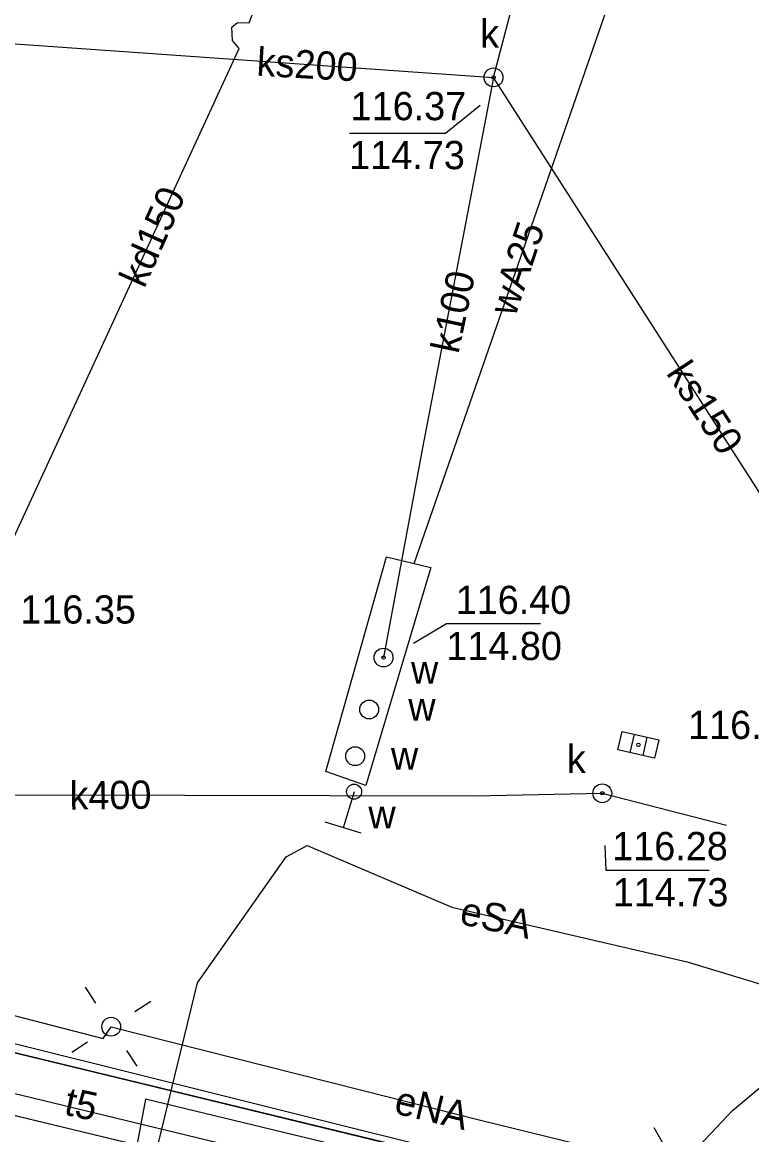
# Model space of a CAD drawing. Extents: x 6424617 to 6425697, y 5665845 to 5667190.
# Drawn here: x 6425547.64 to 6425566.99, y 5666958.69 to 5666988.22 of the extents above; entities that cross this region are included whole.
import ezdxf

# ---------------------------------------------------------------- set-up
doc = ezdxf.new("R2010")
doc.units = 0
for name, color, linetype in [('Warstwa 1', 7, 'Continuous'), ('Warstwa 10', 7, 'Continuous'), ('Warstwa 11', 7, 'Continuous'), ('Warstwa 12', 7, 'Continuous'), ('Warstwa 13', 7, 'Continuous'), ('Warstwa 14', 7, 'Continuous'), ('Warstwa 15', 7, 'Continuous'), ('Warstwa 16', 7, 'Continuous'), ('Warstwa 19', 7, 'Continuous'), ('Warstwa 2', 7, 'Continuous'), ('Warstwa 4', 7, 'Continuous'), ('Warstwa 5', 7, 'Continuous'), ('Warstwa 6', 7, 'Continuous'), ('Warstwa 8', 7, 'Continuous')]:
    doc.layers.add(name, color=color, linetype=linetype)

msp = doc.modelspace()

# ---------------------------------------------------------------- linework, layer by layer
at = {"layer": 'Warstwa 1'}
msp.add_line((6425527.303, 5666965.745), (6425576.814, 5666953.737), dxfattribs=at)
msp.add_line((6425527.303, 5666965.745), (6425576.814, 5666953.737), dxfattribs=at)
at = {"layer": 'Warstwa 10'}
msp.add_lwpolyline([(6425535.744, 5666941.787), (6425536.583, 5666940.695), (6425537.907, 5666939.746), (6425544.265, 5666937.997), (6425545.426, 5666938.203), (6425546.164, 5666939.127), (6425551.078, 5666957.748), (6425552.286, 5666962.717), (6425554.637, 5666966.067), (6425555.195, 5666966.366), (6425559.031, 5666964.726), (6425565.283, 5666963.277), (6425574.202, 5666960.569), (6425578.591, 5666959.798)], dxfattribs=at)
at = {"layer": 'Warstwa 12'}
for points in [[(6425539.125, 5666967.528), (6425537.758, 5666968.09), (6425533.53, 5666969.082), (6425543.916, 5666987.895), (6425560.142, 5666986.759), (6425563.343, 5666998.971), (6425565.066, 5667006.271)], [(6425558.037, 5666973.857), (6425561.357, 5666983.422), (6425564.436, 5666992.303), (6425565.641, 5666995.833)], [(6425539.125, 5666967.528), (6425539.77, 5666967.955), (6425540.466, 5666968.424), (6425545.972, 5666971.519), (6425546.884, 5666973.41), (6425553.39, 5666987.53), (6425553.215, 5666987.735), (6425553.194, 5666988.091), (6425553.348, 5666988.216), (6425553.653, 5666988.212), (6425555.762, 5666993.845)], [(6425560.142, 5666986.759), (6425558.258, 5666976.922), (6425557.223, 5666971.356)], [(6425580.722, 5666968.506), (6425570.322, 5666970.864), (6425560.142, 5666986.759)], [(6425539.125, 5666967.528), (6425540.592, 5666967.708), (6425551.946, 5666967.707), (6425559.628, 5666967.685), (6425563.028, 5666967.753), (6425566.322, 5666966.904)], [(6425526.723, 5666966.717), (6425527.892, 5666964.808), (6425529.009, 5666964.05), (6425530.282, 5666963.934), (6425562.578, 5666956.118), (6425563.973, 5666956.32)], [(6425545.217, 5666962.423), (6425549.784, 5666961.239), (6425549.997, 5666961.555), (6425559.829, 5666959.064), (6425565.028, 5666957.793), (6425566.479, 5666959.332), (6425568.158, 5666960.726)], [(6425578.149, 5666952.974), (6425577.636, 5666953.097), (6425563.178, 5666956.671), (6425550.902, 5666959.63), (6425548.24, 5666945.391)]]:
    msp.add_lwpolyline(points, dxfattribs=at)
at = {"layer": 'Warstwa 14'}
for points in [[(6425556.32, 5666985.282), (6425558.87, 5666985.282), (6425559.789, 5666986.021)], [(6425561.386, 5666972.249), (6425558.896, 5666972.249), (6425558.018, 5666971.734)], [(6425565.863, 5666965.706), (6425563.129, 5666965.706), (6425563.106, 5666966.363)]]:
    msp.add_lwpolyline(points, dxfattribs=at)
for centre in [(6425560.143, 5666986.759), (6425557.223, 5666971.356), (6425563.986, 5666969.039), (6425563.028, 5666967.753)]:
    msp.add_circle(centre, 0.045, dxfattribs=at)
at = {"layer": 'Warstwa 16'}
msp.add_lwpolyline([(6425557.299, 5666974.032), (6425558.481, 5666973.751), (6425556.751, 5666967.964), (6425555.689, 5666968.333)], close=True, dxfattribs=at)
at = {"layer": 'Warstwa 19'}
for p, q in [((6425556.441, 5666967.795), (6425556.152, 5666966.838)), ((6425556.631, 5666966.693), (6425555.674, 5666966.982))]:
    msp.add_line(p, q, dxfattribs=at)
at = {"layer": 'Warstwa 2'}
msp.add_lwpolyline([(6425569.146, 5666955.68), (6425545.086, 5666961.686), (6425545.001, 5666962.231)], dxfattribs=at)
msp.add_circle((6425549.997, 5666961.555), 0.25, dxfattribs=at)
at = {"layer": 'Warstwa 4'}
for p, q in [((6425563.872, 5666969.322), (6425563.759, 5666968.835)), ((6425564.213, 5666969.243), (6425564.1, 5666968.756))]:
    msp.add_line(p, q, dxfattribs=at)
msp.add_lwpolyline([(6425563.555, 5666969.395), (6425564.529, 5666969.17), (6425564.417, 5666968.683), (6425563.443, 5666968.908)], close=True, dxfattribs=at)
for points in [[(6425549.588, 5666962.184), (6425549.316, 5666962.603)], [(6425550.626, 5666961.964), (6425551.045, 5666962.236)], [(6425549.368, 5666961.146), (6425548.949, 5666960.874)], [(6425550.406, 5666960.926), (6425550.678, 5666960.507)], [(6425564.651, 5666958.441), (6425564.4, 5666958.874)]]:
    msp.add_lwpolyline(points, dxfattribs=at)
for centre, radius in [((6425560.142, 5666986.759), 0.25), ((6425557.223, 5666971.356), 0.25), ((6425556.841, 5666969.977), 0.25), ((6425556.471, 5666968.737), 0.25), ((6425556.441, 5666967.795), 0.2), ((6425563.028, 5666967.753), 0.25)]:
    msp.add_circle(centre, radius, dxfattribs=at)
at = {"layer": 'Warstwa 6'}
for points in [[(6425538.589, 5667012.208), (6425527.303, 5666965.745), (6425576.814, 5666953.737), (6425578.804, 5666961.993), (6425586.755, 5666995.159), (6425585.848, 5666995.38), (6425587.284, 5667001.29)], [(6425578.242, 5666953.39), (6425576.814, 5666953.737), (6425527.303, 5666965.745), (6425525.198, 5666957.05), (6425544.583, 5666952.346), (6425576.283, 5666944.651)], [(6425576.587, 5666946.009), (6425553.175, 5666951.612), (6425543.396, 5666954.068), (6425534.357, 5666959.263), (6425535.06, 5666962.181), (6425577.9, 5666951.863)]]:
    msp.add_lwpolyline(points, dxfattribs=at)
at = {"layer": 'Warstwa 8'}
msp.add_line((6425535.06, 5666962.181), (6425565.532, 5666954.842), dxfattribs=at)

# ---------------------------------------------------------------- texts
at = {"layer": 'Warstwa 11'}
msp.add_text('eSA', height=0.75, rotation=347.6421, dxfattribs=at).set_placement((6425559.211, 5666964.29))
at = {"layer": 'Warstwa 13'}
for s, rotation, p in [('ks200', 356.6891, (6425553.841, 5666986.807)), ('kd150', 65.9589, (6425550.873, 5666981.135)), ('wA25', 71.551, (6425560.716, 5666980.383)), ('k100', 78.0712, (6425559.21, 5666979.4)), ('ks150', 303.3296, (6425564.707, 5666978.908)), ('k400', 0.6875, (6425548.894, 5666967.318)), ('t5', 347.6135, (6425548.717, 5666959.228)), ('eNA', 346.4733, (6425557.471, 5666959.264))]:
    msp.add_text(s, height=0.75, rotation=rotation, dxfattribs=at).set_placement(p)
at = {"layer": 'Warstwa 14'}
for s, p in [('114.73', (6425556.313, 5666984.323)), ('114.80', (6425558.888, 5666971.289)), ('114.73', (6425563.306, 5666964.75))]:
    msp.add_text(s, height=0.75, dxfattribs=at).set_placement(p)
at = {"layer": 'Warstwa 15'}
for s, p in [('116.37', (6425556.349, 5666985.623)), ('116.40', (6425559.137, 5666972.513)), ('116.35', (6425547.584, 5666972.259)), ('116.12', (6425565.304, 5666969.194)), ('116.28', (6425563.291, 5666965.977))]:
    msp.add_text(s, height=0.75, dxfattribs=at).set_placement(p)
at = {"layer": 'Warstwa 5'}
for s, p in [('k', (6425559.788, 5666987.546)), ('w', (6425557.951, 5666970.666)), ('w', (6425557.88, 5666969.679)), ('k', (6425562.089, 5666968.291)), ('w', (6425557.419, 5666968.38)), ('w', (6425556.82, 5666966.822))]:
    msp.add_text(s, height=0.75, dxfattribs=at).set_placement(p)

doc.saveas('drawing.dxf')
